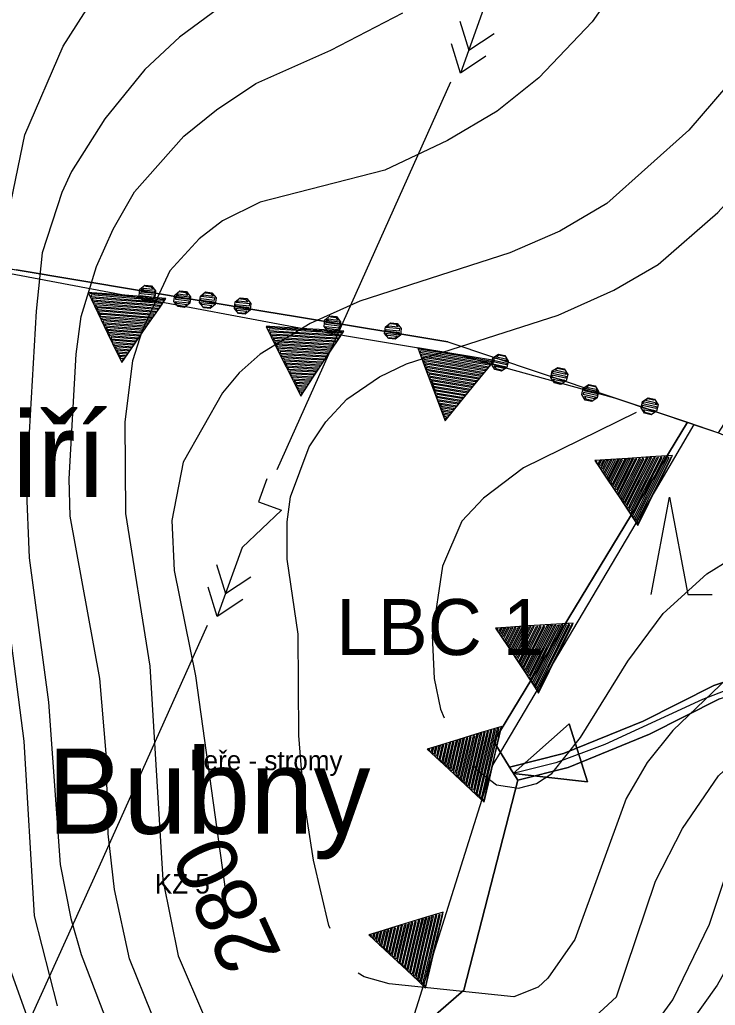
# Model space of a CAD drawing. Extents: x -645676 to -642474, y -1077513 to -1072613.
# Drawn here: x -643321.6 to -643178.8, y -1072932.3 to -1072729.9 of the extents above; entities that cross this region are included whole.
import ezdxf

# ---------------------------------------------------------------- set-up
doc = ezdxf.new("R2010")
doc.units = 0
for name, color, linetype in [('ELEKTRO', 7, 'Continuous'), ('katastr_ln___zem____popis', 7, 'Continuous'), ('Krajinn__zele____popis___stav', 7, 'Continuous'), ('KULTURY_STAV', 7, 'Continuous'), ('KULTURY_ZNACKY', 7, 'Continuous'), ('Lok_ln__biocentrum___st_vaj_c_', 7, 'Continuous'), ('OBVOD_PU', 7, 'Continuous'), ('PC_STAN_STAV', 7, 'Continuous'), ('PC_STAV', 7, 'Continuous'), ('SPRAV_HR_STAV', 7, 'Continuous'), ('USES_BC_STAV', 7, 'Continuous'), ('VRSTEVNICE', 7, 'Continuous'), ('Vrstevnice_zd_razn_n____popis', 7, 'Continuous')]:
    doc.layers.add(name, color=color, linetype=linetype)

# ---------------------------------------------------------------- blocks, each defined once
blk = doc.blocks.new('$945')
for points in [[(0, 0), (-2.8, 1.25), (-2.8, -1.25), (0, 0)], [(-2.8, 1.25), (0, 0), (-2.8, -1.25), (-2.8, 1.25)]]:
    blk.add_lwpolyline(points)
blk = doc.blocks.new('3$0800')
blk.add_lwpolyline([(-0.75, 0), (0, 4), (0.75, 0), (1.75, 0)])
blk = doc.blocks.new('$1193')
for points in [[(2, 0), (0.73, 0), (-0.54, 0), (-1.81, 0), (-2, 0), (-1.43, -1), (-0.85, -2), (-0.27, -3), (0, -3.46), (0.57, -2.46), (1.15, -1.46), (1.73, -0.46), (2, 0)], [(-1.92, -0.04), (-0.65, -0.04), (0.62, -0.04), (1.89, -0.04), (1.92, -0.04), (1.84, -0.12), (0.57, -0.12), (-0.7, -0.12), (-1.84, -0.12), (-1.84, -0.2), (-0.57, -0.2), (0.7, -0.2), (1.84, -0.2), (1.76, -0.28), (0.49, -0.28), (-0.78, -0.28), (-1.76, -0.28), (-1.76, -0.36), (-0.49, -0.36), (0.78, -0.36), (1.76, -0.36), (1.68, -0.44), (0.41, -0.44), (-0.86, -0.44), (-1.68, -0.44), (-1.68, -0.52), (-0.41, -0.52), (0.86, -0.52), (1.68, -0.52), (1.6, -0.6), (0.33, -0.6), (-0.94, -0.6), (-1.6, -0.6), (-1.52, -0.68), (-0.25, -0.68), (1.02, -0.68), (1.52, -0.68), (1.52, -0.76), (0.25, -0.76), (-1.02, -0.76), (-1.52, -0.76), (-1.44, -0.84), (-0.17, -0.84), (1.1, -0.84), (1.44, -0.84), (1.44, -0.92), (0.17, -0.92), (-1.1, -0.92), (-1.44, -0.92), (-1.36, -1), (-0.09, -1), (1.18, -1), (1.36, -1), (1.36, -1.08), (0.09, -1.08), (-1.18, -1.08), (-1.36, -1.08), (-1.28, -1.16), (-0.01, -1.16), (1.26, -1.16), (1.28, -1.16), (1.2, -1.24), (-0.07, -1.24), (-1.2, -1.24), (-1.2, -1.32), (0.07, -1.32), (1.2, -1.32), (1.12, -1.4), (-0.15, -1.4), (-1.12, -1.4), (-1.12, -1.48), (0.15, -1.48), (1.12, -1.48), (1.04, -1.56), (-0.23, -1.56), (-1.04, -1.56), (-0.96, -1.64), (0.31, -1.64), (1.04, -1.64), (0.96, -1.72), (-0.31, -1.72), (-0.96, -1.72), (-0.88, -1.8), (0.39, -1.8), (0.88, -1.8), (0.88, -1.88), (-0.39, -1.88), (-0.88, -1.88), (-0.8, -1.96), (0.47, -1.96), (0.8, -1.96), (0.8, -2.04), (-0.47, -2.04), (-0.8, -2.04), (-0.72, -2.12), (0.55, -2.12), (0.72, -2.12), (0.64, -2.2), (-0.63, -2.2), (-0.64, -2.2), (-0.64, -2.28), (0.63, -2.28), (0.64, -2.28), (0.56, -2.36), (-0.64, -2.36), (-0.56, -2.44), (0.56, -2.44), (0.48, -2.52), (-0.48, -2.52), (-0.48, -2.6), (0.48, -2.6), (0.4, -2.68), (-0.4, -2.68), (-0.32, -2.76), (0.4, -2.76), (0.32, -2.84), (-0.32, -2.84), (-0.24, -2.92), (0.24, -2.92), (0.24, -3), (-0.24, -3), (-0.16, -3.08), (0.16, -3.08), (0.16, -3.16), (-0.16, -3.16), (-0.08, -3.24), (0.08, -3.24), (0.08, -3.32), (0, -3.32), (0, -3.4)]]:
    blk.add_lwpolyline(points)
blk = doc.blocks.new('6$6120')
for points in [[(-3, 0), (-2, 0), (-2, 1), (0, 0), (3, 0)], [(1, -0.75), (2, 0), (1, 0.75)], [(2, 0.75), (3, 0), (2, -0.75)]]:
    blk.add_lwpolyline(points)
blk = doc.blocks.new('2$0620')
for points in [[(-1.07, 0.32), (-0.88, 0.13), (-0.88, -0.14), (-1.07, -0.33), (-1.34, -0.33), (-1.53, -0.14), (-1.53, 0.13), (-1.34, 0.32), (-1.07, 0.32), (-1.08, 0.28), (-1.32, 0.28), (-1.4, 0.2), (-1, 0.2), (-0.92, 0.12), (-1.48, 0.12), (-1.48, 0.04), (-0.92, 0.04), (-0.92, -0.04), (-1.48, -0.04), (-1.48, -0.12), (-0.92, -0.12), (-1, -0.2), (-1.4, -0.2), (-1.32, -0.28), (-1.08, -0.28)], [(1.43, 0.32), (1.62, 0.13), (1.62, -0.14), (1.43, -0.33), (1.16, -0.33), (0.97, -0.14), (0.97, 0.13), (1.16, 0.32), (1.43, 0.32), (1.4, 0.28), (1.16, 0.28), (1.08, 0.2), (1.48, 0.2), (1.56, 0.12), (1, 0.12), (1, 0.04), (1.56, 0.04), (1.56, -0.04), (1, -0.04), (1, -0.12), (1.56, -0.12), (1.48, -0.2), (1.08, -0.2), (1.16, -0.28), (1.4, -0.28)]]:
    blk.add_lwpolyline(points)

msp = doc.modelspace()

# ---------------------------------------------------------------- linework, layer by layer
at = {"layer": 'ELEKTRO'}
for points in [[(-643233.18, -1072742.73), (-643253.51, -1072788.13), (-643268.83, -1072822.36)], [(-643283.13, -1072854.31), (-643305.36, -1072903.97), (-643320.88, -1072938.11)]]:
    msp.add_lwpolyline(points, dxfattribs=at)
at = {"layer": 'KULTURY_STAV'}
for points in [[(-643385.88, -1072863.91), (-643386.46, -1072823.02), (-643372.56, -1072773.44), (-643347.83, -1072776.63), (-643341.24, -1072778.17), (-643233.74, -1072796.06), (-643215.2, -1072802.29), (-643184.53, -1072812.6), (-643224.31, -1072878.16), (-643221.04, -1072883.43), (-643219.38, -1072886.11), (-643230.42, -1072929.19), (-643310.22, -1072998.61)], [(-643184.53, -1072812.6), (-643178.15, -1072814.75), (-643154, -1072825.07), (-643174.9, -1072865.29), (-643179.1, -1072866.62), (-643193.59, -1072873.94), (-643209.99, -1072880.6), (-643221.04, -1072883.43), (-643224.31, -1072878.16), (-643184.53, -1072812.6)], [(-643221.04, -1072883.43), (-643209.99, -1072880.6), (-643193.59, -1072873.94), (-643179.1, -1072866.62), (-643174.9, -1072865.29)], [(-643310.22, -1072998.61), (-643230.42, -1072929.19), (-643219.38, -1072886.11), (-643209.05, -1072883.45), (-643192.35, -1072876.67), (-643177.96, -1072869.41), (-643170.8, -1072867.14), (-643158.09, -1072867.68), (-643130.45, -1072871.44), (-643120.46, -1072872.26), (-643117.11, -1072873.93), (-643114.12, -1072877.99), (-643113.75, -1072882.84), (-643115.1, -1072889.26), (-643119.89, -1072901.94), (-643121.16, -1072909.92), (-643121.08, -1072918.25), (-643119.72, -1072929.35), (-643130.56, -1072946.95)], [(-643177.96, -1072869.41), (-643192.35, -1072876.67), (-643209.05, -1072883.45), (-643219.38, -1072886.11), (-643221.04, -1072883.43)]]:
    msp.add_lwpolyline(points, dxfattribs=at)
at = {"layer": 'OBVOD_PU'}
msp.add_lwpolyline([(-643452.62, -1072953.74), (-643455.92, -1072900.92), (-643415.32, -1072890.43), (-643385.62, -1072882.75), (-643386.46, -1072823.02), (-643372.56, -1072773.44), (-643350.57, -1072776.28), (-643347.83, -1072776.63), (-643341.24, -1072778.17), (-643322.37, -1072781.31), (-643271.73, -1072789.74), (-643264.57, -1072790.93), (-643233.74, -1072796.06), (-643215.2, -1072802.29), (-643184.53, -1072812.6), (-643182.86, -1072813.16), (-643178.15, -1072814.75), (-643148.44, -1072768.25), (-643130.71, -1072775.14), (-643111.2, -1072753.98)], dxfattribs=at)
at = {"layer": 'PC_STAV'}
msp.add_lwpolyline([(-643118.36, -1072926.82), (-643119.77, -1072910.53), (-643118.52, -1072901.91), (-643112.57, -1072886.09), (-643113.04, -1072877.95), (-643117.11, -1072872.15), (-643124.63, -1072870.12), (-643160.79, -1072866.05), (-643171.75, -1072865.73), (-643181.46, -1072869.49), (-643201.5, -1072878.73), (-643211.52, -1072882.49), (-643220.28, -1072884.68)], dxfattribs=at)
at = {"layer": 'SPRAV_HR_STAV'}
for p, q in [((-643271.73, -1072789.74), (-643322.37, -1072781.31)), ((-643264.57, -1072790.93), (-643271.73, -1072789.74)), ((-643233.74, -1072796.06), (-643264.57, -1072790.93)), ((-643233.74, -1072796.06), (-643215.2, -1072802.29)), ((-643215.2, -1072802.29), (-643184.53, -1072812.6)), ((-643184.53, -1072812.6), (-643182.86, -1072813.16)), ((-643182.86, -1072813.16), (-643178.15, -1072814.75))]:
    msp.add_line(p, q, dxfattribs=at)
at = {"layer": 'USES_BC_STAV'}
msp.add_lwpolyline([(-643375.84, -1072948.54), (-643381.16, -1072924.14), (-643385.03, -1072902.59), (-643385.62, -1072882.75), (-643385.9, -1072870.38), (-643386.01, -1072852.87), (-643386.46, -1072823.02), (-643381.53, -1072806.13), (-643379.51, -1072798.23), (-643372.56, -1072773.44), (-643367.34, -1072774.11), (-643357.01, -1072775.45), (-643333.38, -1072780.21), (-643299.57, -1072786.55), (-643263.06, -1072793.39), (-643232.02, -1072798.62), (-643199.48, -1072807.58), (-643183.23, -1072813.04), (-643191.15, -1072826.6), (-643222.89, -1072880.24), (-643224.46, -1072882.84), (-643271.31, -1073031.69)], dxfattribs=at)
at = {"layer": 'VRSTEVNICE'}
for points in [[(-643313.86, -1072932.44), (-643318.56, -1072913.93), (-643320.7, -1072878.04), (-643324.69, -1072847.28), (-643325.12, -1072837.02), (-643324.4, -1072816.51), (-643325.4, -1072783.47), (-643323.83, -1072769.51), (-643320.56, -1072753.56), (-643312.72, -1072735.33), (-643301.05, -1072717.1), (-643294.64, -1072705.71), (-643291.36, -1072696.6), (-643290.08, -1072689.76), (-643289.51, -1072677.79), (-643292.07, -1072662.98), (-643298.48, -1072644.75), (-643304.61, -1072631.08), (-643307.46, -1072626.52), (-643315.86, -1072618.41), (-643323.26, -1072615.27), (-643340.42, -1072613.42)], [(-643168.46, -1072613.42), (-643166.6, -1072621.11), (-643159.91, -1072637.35), (-643145.95, -1072664.41), (-643142.67, -1072675.23), (-643142.39, -1072686.05), (-643143.24, -1072691.47), (-643145.09, -1072696.88), (-643147.94, -1072702.29), (-643173.72, -1072740.32), (-643184.26, -1072752.57), (-643201.07, -1072767.66), (-643210.75, -1072773.36), (-643221.01, -1072777.77), (-643251.77, -1072787.74), (-643262.02, -1072792.3), (-643272.28, -1072798.57), (-643276.55, -1072802.41), (-643279.97, -1072806.54), (-643288.09, -1072820.79), (-643290.36, -1072832.75), (-643289.94, -1072843), (-643285.52, -1072864.65), (-643279.36, -1072908.92)], [(-643299.22, -1072973.72), (-643302.19, -1072970.61), (-643310.16, -1072958.65), (-643316, -1072946.12), (-643325.68, -1072919.06), (-643329.1, -1072897.41), (-643332.38, -1072837.88), (-643330.1, -1072810.82), (-643331.52, -1072778.34), (-643327.25, -1072740.46), (-643323.26, -1072724.22), (-643317, -1072703.43), (-643314.86, -1072682.92), (-643315.43, -1072672.67), (-643318.28, -1072657.29), (-643321.98, -1072647.03), (-643324.55, -1072641.91), (-643330.95, -1072632.36), (-643336.58, -1072627.91), (-643341.24, -1072625.06)], [(-643034.84, -1072665.7), (-643044.26, -1072701.72), (-643055.65, -1072737.04), (-643061.21, -1072747.58), (-643078.44, -1072775.21), (-643088.92, -1072786.35), (-643096.42, -1072795.41), (-643101.08, -1072800.07), (-643119.89, -1072835.88), (-643126.15, -1072852.4), (-643132.13, -1072863.8), (-643138.97, -1072872.2), (-643152.36, -1072885.16), (-643159.05, -1072893.56), (-643178.42, -1072928.17), (-643192.81, -1072948.4)], [(-643191.38, -1072936.43), (-643187.54, -1072931.16), (-643179.99, -1072915.64), (-643173.72, -1072896.84), (-643168.02, -1072887.44), (-643158.34, -1072876.9), (-643141.39, -1072861.66), (-643135.13, -1072853.69), (-643128.86, -1072841.58), (-643124.3, -1072829.62), (-643115.33, -1072809.68), (-643108.07, -1072797), (-643107.07, -1072796.72), (-643092.26, -1072780.05), (-643073.88, -1072752.14), (-643059.5, -1072731.63), (-643048.82, -1072702.86), (-643042.09, -1072674.79)], [(-643265.31, -1072938.69), (-643262.76, -1072941.07), (-643255.76, -1072942.7), (-643239.81, -1072941.99), (-643223.85, -1072942.27), (-643213.03, -1072940.71), (-643207.76, -1072938.57), (-643199.07, -1072930.59), (-643191.1, -1072906.81), (-643185.54, -1072895.98), (-643178.14, -1072885.16), (-643169.73, -1072877.33), (-643157.34, -1072867.64), (-643153.36, -1072863.8), (-643146.66, -1072855.25), (-643138.4, -1072840.58), (-643125.73, -1072814.09), (-643121.31, -1072803.13), (-643115.76, -1072792.3), (-643108.07, -1072781.62), (-643076.16, -1072742.31), (-643069.18, -1072732.2), (-643054.25, -1072701.45), (-643050.11, -1072685.4)], [(-643273.99, -1072722.51), (-643288.8, -1072733.48), (-643295.92, -1072740.18), (-643304.18, -1072750.29), (-643311.02, -1072761.11), (-643313.01, -1072765.38), (-643317, -1072777.77), (-643318.28, -1072789.74), (-643320.27, -1072825.34), (-643319.7, -1072840.44), (-643315.72, -1072870.06), (-643313.29, -1072903.39), (-643311.16, -1072914.5), (-643309.02, -1072921.91), (-643303.32, -1072936.72)], [(-643199.22, -1072723.37), (-643204.06, -1072730.35), (-643215.02, -1072741.88), (-643223.57, -1072748.72), (-643233.82, -1072754.7), (-643246.64, -1072760.83), (-643272.28, -1072767.38), (-643279.97, -1072771.22), (-643284.81, -1072774.93), (-643290.79, -1072781.48), (-643296.49, -1072793.73), (-643298.48, -1072799.99), (-643300.05, -1072812.53), (-643299.91, -1072831.33), (-643294.92, -1072862.66), (-643292.22, -1072906.52), (-643289.08, -1072922.19), (-643283.67, -1072934.72)], [(-643294.49, -1072934.15), (-643299.05, -1072922.76), (-643302.19, -1072908.52), (-643303.47, -1072897.12), (-643303.89, -1072880.6), (-643305.18, -1072865.22), (-643311.3, -1072831.9), (-643311.44, -1072824.2), (-643310.02, -1072798.57), (-643309.02, -1072790.88), (-643305.89, -1072780.62), (-643302.47, -1072772.93), (-643298.06, -1072765.24), (-643287.94, -1072753.85), (-643281.25, -1072748.44), (-643273.13, -1072743.02), (-643257.75, -1072736.19), (-643242.94, -1072728.5)], [(-643257.91, -1072916.52), (-643258.18, -1072915.92), (-643261.31, -1072902.54), (-643263.3, -1072889.72), (-643264.3, -1072876.9), (-643264.44, -1072856.11), (-643266.72, -1072840.73), (-643266.72, -1072833.03), (-643266.01, -1072827.91), (-643262.17, -1072817.65), (-643258.75, -1072812.53), (-643254.47, -1072807.83), (-643247.78, -1072803.27), (-643242.23, -1072800.56), (-643211.04, -1072790.59), (-643199.64, -1072785.47), (-643190.53, -1072780.2), (-643178.28, -1072769.51), (-643167.6, -1072757.84), (-643148.51, -1072729.64)], [(-643228.28, -1072883.3), (-643227.84, -1072883.88), (-643223.71, -1072887.01), (-643219.24, -1072887.74), (-643215.49, -1072886.77), (-643212.34, -1072884.71), (-643206.48, -1072877.33), (-643196.79, -1072861.66), (-643189.53, -1072851.83), (-643180.56, -1072843.72), (-643175.72, -1072840.73), (-643164.61, -1072835.6), (-643157.77, -1072829.9), (-643150.36, -1072819.93), (-643137.12, -1072796.86), (-643129.71, -1072786.61), (-643126.13, -1072782.51), (-643119.91, -1072772.17), (-643111.38, -1072753.79), (-643103.87, -1072731.01)], [(-643104.91, -1072766.68), (-643113.6, -1072775.82), (-643121.31, -1072785.61), (-643131, -1072803.98), (-643142.67, -1072829.62), (-643150.36, -1072841.86), (-643158.06, -1072849.55), (-643169.73, -1072858.81), (-643187.54, -1072875.9), (-643192.81, -1072882.45), (-643197.08, -1072889.86), (-643207.62, -1072918.77), (-643213.17, -1072926.75), (-643215.17, -1072928.6), (-643220.15, -1072930.59), (-643245.79, -1072927.89), (-643250.91, -1072926.46), (-643252.1, -1072925.69)], [(-643195.08, -1072810.61), (-643218.16, -1072821.93), (-643226.42, -1072828.19), (-643230.83, -1072832.89), (-643234.82, -1072842.15), (-643236.96, -1072856.39), (-643236.53, -1072865.22), (-643235.25, -1072871.49), (-643234.46, -1072873.31)]]:
    msp.add_lwpolyline(points, dxfattribs=at)

# ---------------------------------------------------------------- block references
at = {"layer": 'ELEKTRO', "xscale": 5}
for p, yscale, rotation in [((-643226.03, -1072726.76), 4.999999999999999, -109.82913300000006), ((-643275.98, -1072838.33), 5, -109.82274000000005)]:
    msp.add_blockref('6$6120', p, dxfattribs=dict(at, yscale=yscale, rotation=rotation))
at = {"layer": 'KULTURY_ZNACKY', "xscale": 5, "yscale": 5}
msp.add_blockref('3$0800', (-643188.22, -1072847.95), dxfattribs=at)
at = {"layer": 'PC_STAN_STAV', "xscale": 5.000000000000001, "yscale": 5, "rotation": -162.56968800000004}
msp.add_blockref('$945', (-643220.28, -1072884.68), dxfattribs=at)
at = {"layer": 'SPRAV_HR_STAV'}
for p, xscale, yscale, rotation in [((-643288.99, -1072786.87), 5.000000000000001, 4.999999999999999, 173.525326), ((-643281.83, -1072788.06), 5.000000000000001, 5, 173.540531), ((-643251, -1072793.19), 5, 5, 173.529454), ((-643217.15, -1072801.63), 5.000000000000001, 5, -12.614887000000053), ((-643198.61, -1072807.87), 5, 5, -12.621641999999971)]:
    msp.add_blockref('2$0620', p, dxfattribs=dict(at, xscale=xscale, yscale=yscale, rotation=rotation))
at = {"layer": 'USES_BC_STAV'}
for p, xscale, yscale, rotation in [((-643299.57, -1072786.55), 4, 4, -4.5178930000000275), ((-643263.06, -1072793.39), 4, 4.000000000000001, -3.4477970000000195), ((-643232.02, -1072798.62), 4, 4, -9.378135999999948), ((-643191.15, -1072826.6), 4, 4, -116.43567600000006), ((-643211.52, -1072861.02), 4, 4, -116.43567600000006), ((-643224.46, -1072882.84), 3.9999999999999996, 4.000000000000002, -103.06375500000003), ((-643236.47, -1072920.99), 3.9999999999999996, 4.000000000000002, -103.06375500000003)]:
    msp.add_blockref('$1193', p, dxfattribs=dict(at, xscale=xscale, yscale=yscale, rotation=rotation))

# ---------------------------------------------------------------- texts
at = {"layer": 'katastr_ln___zem____popis'}
for s, p in [('sv. Jiří', (-643371.27, -1072827.95)), ('Tři Bubny', (-643349.74, -1072897.09))]:
    msp.add_text(s, height=17.5, dxfattribs=at).set_placement(p)
at = {"layer": 'Krajinn__zele____popis___stav'}
for s, p in [('keře - stromy', (-643286.55, -1072884.03)), ('KZ 5', (-643293.89, -1072909.36))]:
    msp.add_text(s, height=4, dxfattribs=at).set_placement(p)
at = {"layer": 'Lok_ln__biocentrum___st_vaj_c_'}
msp.add_text('LBC 1', height=11.5, dxfattribs=at).set_placement((-643256.66, -1072860.39))
at = {"layer": 'Vrstevnice_zd_razn_n____popis'}
msp.add_text('280', height=12.5, rotation=114.592, dxfattribs=at).set_placement((-643267.72, -1072921.83))

doc.saveas('drawing.dxf')
